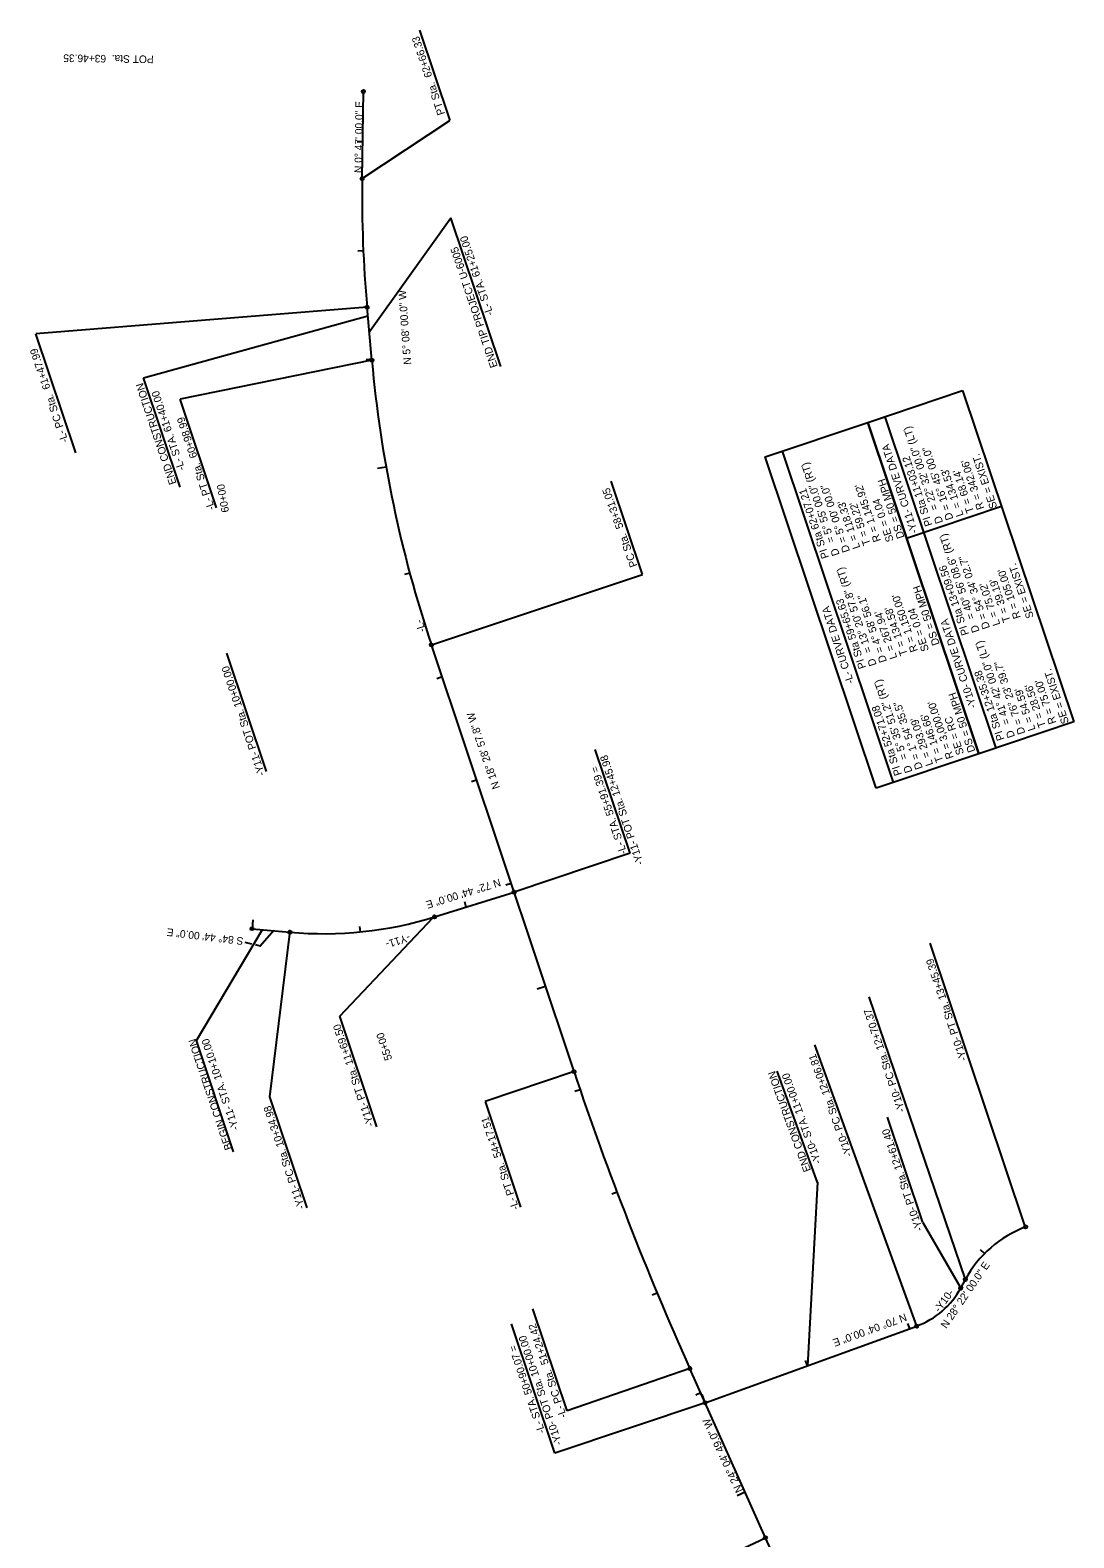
# Model space of a CAD drawing. Extents: x 1615712 to 1617175, y 899615 to 904865.
# Drawn here: x 1615712 to 1616671, y 903479 to 904865 of the extents above; entities that cross this region are included whole.
import ezdxf

# ---------------------------------------------------------------- set-up
doc = ezdxf.new("R2010")
doc.units = 0
for name, color, linetype in [('Prop Horizontal Alignment', 7, 'Continuous'), ('Prop Horizontal Alignment Curve and Spiral Data', 7, 'Continuous'), ('Prop Horizontal Alignment Direction Label', 7, 'Continuous'), ('Prop Horizontal Alignment Station Label', 7, 'Continuous'), ('Prop Horizontal Alignment Tick Label', 7, 'Continuous'), ('Prop Horizontal Alignment Tick Large', 7, 'Continuous'), ('Prop Horizontal Alignment Tick Small', 7, 'Continuous'), ('Scratch_Level_0', 7, 'Continuous')]:
    doc.layers.add(name, color=color, linetype=linetype)

msp = doc.modelspace()

# ---------------------------------------------------------------- linework, layer by layer
at = {"layer": 'Prop Horizontal Alignment'}
for p, q in [((1616017.4, 904728.1), (1616018.5, 904808.1)), ((1616017.4, 904728.1), (1616018.5, 904808.1)), ((1616026.3, 904561.1), (1616021.9, 904609.9)), ((1616026.3, 904561.1), (1616021.9, 904609.9)), ((1616212.1, 903907.2), (1616081, 904299.4)), ((1616212.1, 903907.2), (1616081, 904299.4)), ((1616083.9, 904049.4), (1616157, 904072.1)), ((1615916.2, 904038.6), (1615951, 904035.4)), ((1616567.3, 903708.2), (1616571.5, 903716.1)), ((1616567.3, 903708.2), (1616571.5, 903716.1)), ((1616332.4, 903602.8), (1616526.9, 903673.3)), ((1616387.9, 903478.7), (1616318.4, 903634.2)), ((1616387.9, 903478.7), (1616318.4, 903634.2))]:
    msp.add_line(p, q, dxfattribs=at)
for centre, radius, start, end in [((1617163.2, 904712.4), 1145.9, 179.2167, 185.1333), ((1617163.2, 904712.4), 1145.9, 179.2167, 185.1333), ((1617171.7, 904664), 1150, 185.1333, 198.4827), ((1617171.7, 904664), 1150, 185.1333, 198.4827), ((1615982.4, 904376.1), 342.1, 264.7333, 287.2667), ((1619057.3, 904858.2), 3000, 198.4827, 204.0803), ((1619057.3, 904858.2), 3000, 198.4827, 204.0803), ((1616663.9, 903666.2), 105, 110.6976, 151.6333), ((1616501.3, 903743.9), 75, 289.9333, 331.6333), ((1613649, 902254.6), 3000, 19.5707, 24.0803), ((1613649, 902254.6), 3000, 19.5707, 24.0803)]:
    msp.add_arc(centre, radius, start, end, dxfattribs=at)
at = {"layer": 'Prop Horizontal Alignment Curve and Spiral Data'}
for p, q in [((1616070.1, 904864.6), (1616097.9, 904781.6)), ((1616144.8, 904555.3), (1616098.8, 904692.2)), ((1615754.3, 904476), (1615717.7, 904585.3)), ((1615883.6, 904425.5), (1615850.1, 904525.4)), ((1616481.8, 904504), (1616569, 904533.2)), ((1616569, 904533.2), (1616671.2, 904228.7)), ((1616583.9, 904199.4), (1616481.8, 904504)), ((1616274.9, 904364.2), (1616246, 904450.1)), ((1616517.4, 904397.7), (1616604.6, 904427)), ((1616671.2, 904228.7), (1616583.9, 904199.4)), ((1616263.5, 904108), (1616157, 904072.1)), ((1615996.9, 903958.2), (1616082.5, 904049)), ((1615865.1, 903935.7), (1615925.7, 904037.8)), ((1615932.7, 903884.1), (1615951, 904033.9)), ((1616130.4, 903879.9), (1616163, 903782.6)), ((1616435.8, 903805.5), (1616426.4, 903636.9)), ((1616318.4, 903634.2), (1616205.8, 903595.3)), ((1616332.4, 903602.8), (1616194.4, 903556.4)), ((1616184.6, 903383.4), (1616387.9, 903478.7))]:
    msp.add_line(p, q, dxfattribs=at)
for points in [[(1616489.6, 904167.8), (1616387.5, 904472.3), (1616481.8, 904504), (1616583.9, 904199.4)], [(1616583.9, 904199.4), (1616481.8, 904504), (1616497.5, 904509.2), (1616599.6, 904204.7)], [(1616489.6, 904167.8), (1616387.5, 904472.3), (1616403.1, 904477.6), (1616505.3, 904173)]]:
    msp.add_lwpolyline(points, close=True, dxfattribs=at)
for points in [[(1615916.1, 904024.5), (1615909.9, 904026)], [(1615936.3, 904036.8), (1615923.8, 904022.5), (1615919.3, 904023.7)]]:
    msp.add_lwpolyline(points, dxfattribs=at)
at = {"layer": 'Prop Horizontal Alignment Station Label'}
for p, q in [((1616017.4, 904728.1), (1616097.9, 904781.6)), ((1616023.4, 904586.8), (1616098.8, 904692.2)), ((1616021.9, 904609.9), (1615717.7, 904585.3)), ((1616026.3, 904561.1), (1616021.9, 904609.9)), ((1616026.3, 904561.1), (1616021.9, 904609.9)), ((1616026.3, 904561.1), (1616021.9, 904609.9)), ((1615816.5, 904545), (1616022.6, 904601.9)), ((1616026.3, 904561.1), (1615850.1, 904525.4)), ((1615850.1, 904444.6), (1615816.5, 904545)), ((1616081, 904299.4), (1616274.9, 904364.2)), ((1615929.5, 904183.1), (1615893, 904291.9)), ((1616212.1, 903907.2), (1616081, 904299.4)), ((1616212.1, 903907.2), (1616081, 904299.4)), ((1616212.1, 903907.2), (1616081, 904299.4)), ((1616263.5, 904108), (1616231.5, 904203.4)), ((1616626.3, 903765.9), (1616539.3, 904025.2)), ((1616571.5, 903716.1), (1616483.2, 903976.1)), ((1616031, 903856.6), (1615996.9, 903958.2)), ((1615899.3, 903833.6), (1615865.1, 903935.7)), ((1616526.9, 903673.3), (1616433.1, 903931.9)), ((1616212.1, 903907.2), (1616130.4, 903879.9)), ((1616435.8, 903805.3), (1616398.7, 903907.6)), ((1615967, 903782.1), (1615932.7, 903884.1)), ((1616532.3, 903768.6), (1616499.9, 903865.3)), ((1616532.3, 903768.6), (1616567.3, 903708.2)), ((1616205.8, 903595.3), (1616174.3, 903689.2)), ((1616194.4, 903556.4), (1616154.5, 903675.3)), ((1616387.9, 903478.7), (1616318.4, 903634.2)), ((1616387.9, 903478.7), (1616318.4, 903634.2)), ((1616387.9, 903478.7), (1616318.4, 903634.2))]:
    msp.add_line(p, q, dxfattribs=at)
for centre in [(1616018.5, 904808.1), (1616017.4, 904728.1), (1616021.9, 904609.9), (1616026.3, 904561.1), (1616081, 904299.4), (1616157, 904072.1), (1615916.2, 904038.6), (1616083.9, 904049.4), (1615951, 904035.4), (1616212.1, 903907.2), (1616626.8, 903764.5), (1616567.3, 903708.2), (1616571.5, 903716.1), (1616526.9, 903673.3), (1616318.4, 903634.2), (1616332.4, 903602.8), (1616387.9, 903478.7)]:
    msp.add_circle(centre, 1.5, dxfattribs=at)
for centre, radius, start, end in [((1617163.2, 904712.4), 1145.9, 179.2167, 185.1333), ((1617163.2, 904712.4), 1145.9, 179.2167, 185.1333), ((1617163.2, 904712.4), 1145.9, 179.2167, 185.1333), ((1617171.7, 904664), 1150, 185.1333, 198.4827), ((1617171.7, 904664), 1150, 185.1333, 198.4827), ((1617171.7, 904664), 1150, 185.1333, 198.4827), ((1619057.3, 904858.2), 3000, 198.4827, 204.0803), ((1619057.3, 904858.2), 3000, 198.4827, 204.0803), ((1619057.3, 904858.2), 3000, 198.4827, 204.0803), ((1616663.9, 903666.2), 105, 110.6976, 151.6333), ((1616501.3, 903743.9), 75, 289.9333, 331.6333)]:
    msp.add_arc(centre, radius, start, end, dxfattribs=at)
at = {"layer": 'Prop Horizontal Alignment Tick Large'}
for p, q in [((1616039.4, 904463), (1616031.5, 904461.6)), ((1615916.9, 904046.6), (1615916.2, 904038.6)), ((1616185.9, 903985.4), (1616178.3, 903982.9)), ((1616332.4, 903602.8), (1616329.7, 903610.4)), ((1616369.2, 903520.6), (1616361.9, 903517.3))]:
    msp.add_line(p, q, dxfattribs=at)
at = {"layer": 'Prop Horizontal Alignment Tick Small'}
for p, q in [((1616017.9, 904761.8), (1616012.9, 904761.8)), ((1616018.4, 904661.8), (1616013.4, 904661.5)), ((1616026.2, 904562.1), (1616021.2, 904561.6)), ((1616061.1, 904365.4), (1616056.3, 904364.1)), ((1616090.8, 904270), (1616086.1, 904268.4)), ((1616122.5, 904175.1), (1616117.8, 904173.5)), ((1616154.2, 904080.3), (1616149.5, 904078.7)), ((1616113, 904058.5), (1616111.6, 904063.2)), ((1616015.9, 904035.6), (1616015.4, 904040.6)), ((1616217.7, 903890.6), (1616212.9, 903889)), ((1616251.5, 903796.5), (1616246.8, 903794.7)), ((1616589.1, 903739.9), (1616585.5, 903743.4)), ((1616288.5, 903703.6), (1616283.8, 903701.7)), ((1616520.4, 903671), (1616518.7, 903675.7)), ((1616426.4, 903636.9), (1616424.7, 903641.6)), ((1616328.4, 903611.9), (1616323.8, 903609.9))]:
    msp.add_line(p, q, dxfattribs=at)
at = {"layer": 'Scratch_Level_0'}
for p, q in [((1616017.4, 904728.1), (1616018.5, 904808.1)), ((1616026.3, 904561.1), (1616021.9, 904609.9)), ((1616026.3, 904561.1), (1616021.9, 904609.9)), ((1616212.1, 903907.2), (1616081, 904299.4)), ((1616212.1, 903907.2), (1616081, 904299.4)), ((1616387.9, 903478.7), (1616318.4, 903634.2)), ((1616387.9, 903478.7), (1616318.4, 903634.2))]:
    msp.add_line(p, q, dxfattribs=at)
for centre, radius, start, end in [((1617163.2, 904712.4), 1145.9, 179.2167, 185.1333), ((1617163.2, 904712.4), 1145.9, 179.2167, 185.1333), ((1617171.7, 904664), 1150, 185.1333, 198.4827), ((1617171.7, 904664), 1150, 185.1333, 198.4827), ((1619057.3, 904858.2), 3000, 198.4827, 204.0803), ((1619057.3, 904858.2), 3000, 198.4827, 204.0803)]:
    msp.add_arc(centre, radius, start, end, dxfattribs=at)

# ---------------------------------------------------------------- texts
at = {"layer": 'Prop Horizontal Alignment Curve and Spiral Data'}
for s, rotation, p in [('= 22%%d 32\' 00.0" (LT)', 108.5432, (1616546.7, 904424.4)), ('-Y11- CURVE DATA', 108.1762, (1616527.9, 904403.2)), ('PI Sta 11+03.12', 108.5432, (1616541.4, 904409.8)), ('D = 16%%d 45\' 00.0"', 108.5432, (1616560.6, 904415.5)), ('SE = EXIST.', 108.5432, (1616600.9, 904426)), ('= 5%%d 55\' 00.0" (RT)', 108.5432, (1616451.7, 904394.7)), ("L = 134.53'", 108.5432, (1616570, 904418.7)), ("T = 68.14'", 108.5432, (1616579.5, 904421.9)), ("R = 342.06'", 108.5432, (1616589, 904425.1)), ('PI Sta 62+07.21', 108.5432, (1616446.4, 904380.1)), ('D = 5%%d 00\' 00.0"', 108.5432, (1616465.6, 904385.8)), ("R = 1,145.92'", 108.5432, (1616494, 904395.4)), ('DS = 50 MPH', 108.5432, (1616515.7, 904398.5)), ("L = 118.33'", 108.5432, (1616475, 904389)), ("T = 59.22'", 108.5432, (1616484.5, 904392.2)), ('SE = 0.04', 108.5432, (1616505.8, 904395.4)), ('D', 108.5432, (1616551.1, 904412.3)), ('= 40%%d 56\' 08.6" (RT)', 108.5432, (1616580.3, 904324.2)), ('D', 108.5432, (1616456.1, 904382.6)), ('PI Sta 13+09.56', 108.5432, (1616575, 904309.5)), ('D = 54%%d 34\' 02.7"', 108.5432, (1616594.2, 904315.3)), ('SE = EXIST.', 108.5432, (1616634.5, 904325.1)), ('= 13%%d 20\' 57.8" (RT)', 108.5432, (1616485.7, 904293.4)), ("T = 39.19'", 108.5432, (1616613.1, 904321.6)), ("R = 105.00'", 108.5432, (1616622.6, 904324.8)), ('D = 4%%d 58\' 56.1"', 108.5432, (1616499.5, 904284.5)), ("R = 1,150.00'", 108.5432, (1616528, 904294.1)), ('DS = 50 MPH', 108.5432, (1616548, 904300.3)), ("L = 75.02'", 108.5432, (1616603.7, 904318.4)), ('-L- CURVE DATA', 108.1762, (1616469.3, 904265)), ('PI Sta 59+65.63', 108.5432, (1616480.4, 904278.8)), ("T = 134.58'", 108.5432, (1616518.5, 904290.9)), ('SE = 0.04', 108.5432, (1616538.2, 904294.8)), ("L = 267.94'", 108.5432, (1616509, 904287.7)), ('-Y10- CURVE DATA', 108.1762, (1616581.8, 904242.5)), ('D', 108.5432, (1616584.7, 904312.1)), ('= 41%%d 42\' 00.0" (LT)', 108.5432, (1616612.8, 904227.4)), ('D', 108.5432, (1616490.1, 904281.3)), ('PI Sta 12+35.38', 108.5432, (1616607.5, 904212.8)), ('D = 76%%d 23\' 39.7"', 108.5432, (1616626.7, 904218.5)), ('SE = EXIST.', 108.5432, (1616666.8, 904228.2)), ('= 5%%d 35\' 51.2" (RT)', 108.5432, (1616518.6, 904195.2)), ("T = 28.56'", 108.5432, (1616645.6, 904224.8)), ("R = 75.00'", 108.5432, (1616655.1, 904228)), ('DS = 50 MPH', 108.5432, (1616580.8, 904202)), ("L = 54.59'", 108.5432, (1616636.1, 904221.7)), ('PI Sta 52+71.08', 108.5432, (1616513.3, 904180.6)), ('D = 1%%d 54\' 35.5"', 108.5432, (1616532.5, 904186.3)), ("T = 146.66'", 108.5432, (1616551.4, 904192.7)), ("R = 3,000.00'", 108.5432, (1616560.9, 904195.9)), ('SE = RC', 108.5432, (1616570.4, 904199.7)), ("L = 293.09'", 108.5432, (1616542, 904189.5)), ('D', 108.5432, (1616617.2, 904215.3)), ('D', 108.5432, (1616523, 904183.1))]:
    msp.add_text(s, height=7, rotation=rotation, dxfattribs=at).set_placement(p)
at = {"layer": 'Prop Horizontal Alignment Direction Label'}
for s, rotation, p in [('N 0%%d 47\' 00.0" E', 89.2167, (1616017.3, 904733.2)), ('N 0%%d 47\' 00.0" E', 89.2167, (1616017.3, 904733.2)), ('N 5%%d 08\' 00.0" W', 94.0743, (1616062.5, 904557.3)), ('N 18%%d 28\' 57.8" W', 108.9866, (1616144, 904168.3)), ('N 72%%d 44\' 00.0" E', 197.2667, (1616143.4, 904084.7)), ('S 84%%d 44\' 00.0" E', 173.0738, (1615908.6, 904030.5)), ('N 28%%d 22\' 00.0" E', 55.6698, (1616554.1, 903670.5)), ('N 70%%d 04\' 00.0" E', 199.9333, (1616516.1, 903685.1)), ('N 24%%d 04\' 49.0" W', 114.7889, (1616367.3, 903522.1))]:
    msp.add_text(s, height=7, rotation=rotation, dxfattribs=at).set_placement(p)
at = {"layer": 'Prop Horizontal Alignment Station Label'}
for s, rotation, p in [('PT Sta.  62+66.33', 108.5432, (1616093.5, 904787.8)), ('POT Sta.  63+46.35', 179.2167, (1615825.9, 904841.2)), ('END TIP PROJECT U-6005', 108.5432, (1616142, 904555.6)), ('-L- STA. 61+25.00', 108.5432, (1616138, 904603.4)), ('-L- PC Sta.  61+47.99', 108.5432, (1615747.5, 904486.7)), ('END CONSTRUCTION', 108.5432, (1615847, 904448.2)), ('-L- STA. 61+40.00', 108.5432, (1615854.7, 904461)), ('-L- PT Sta.  60+98.99', 108.5432, (1615882.2, 904424.6)), ('PC Sta.  58+31.05', 109.8128, (1616270.3, 904372.3)), ('-Y11- POT Sta. 10+00.00', 108.5432, (1615928.3, 904180.4)), ('-Y11- POT Sta. 12+45.98', 108.5432, (1616276, 904098.5)), ('-L- STA. 55+91.39 =', 108.5432, (1616260.7, 904108.2)), ('-Y10- PT Sta. 13+45.39', 108.5432, (1616573.1, 903918.3)), ('-Y10- PC Sta. 12+70.37', 108.5432, (1616516.3, 903871.2)), ('-Y11- PT Sta. 11+69.50', 108.5432, (1616028.4, 903858.1)), ('BEGIN CONSTRUCTION', 108.5432, (1615898.3, 903836.5)), ('-Y11- STA. 10+10.00 ', 108.5432, (1615904.3, 903854.6)), ('-Y10- PC Sta. 12+06.81', 109.9333, (1616467.8, 903830.4)), ('END CONSTRUCTION', 109.9333, (1616429.8, 903816.5)), ('-Y10- STA. 11+00.00', 109.9333, (1616439.3, 903823.7)), ('-Y11- PC Sta. 10+34.98', 108.5432, (1615964.9, 903782)), ('-L- PT Sta.  54+17.51', 108.5432, (1616161.6, 903781.4)), ('-Y10- PT Sta. 12+61.40', 108.5432, (1616532.6, 903761.9)), ('-L- PC Sta.  51+24.42', 108.5432, (1616205.4, 903590.2)), ('-L- STA. 50+90.07 =', 108.5432, (1616185.6, 903576)), ('-Y10- POT Sta. 10+00.00', 108.5432, (1616201.2, 903565))]:
    msp.add_text(s, height=7, rotation=rotation, dxfattribs=at).set_placement(p)
at = {"layer": 'Prop Horizontal Alignment Tick Label'}
for s, rotation, p in [('60+00', 100.0651, (1615895.2, 904421.9)), ('-L-', 107.128, (1616075.8, 904312.4)), ('-Y11-', 197.6022, (1616060.2, 904034)), ('55+00', 108.4827, (1616045.1, 903918.8)), ('-Y10-', 53.5146, (1616547.7, 903685.4))]:
    msp.add_text(s, height=7, rotation=rotation, dxfattribs=at).set_placement(p)

doc.saveas('drawing.dxf')
